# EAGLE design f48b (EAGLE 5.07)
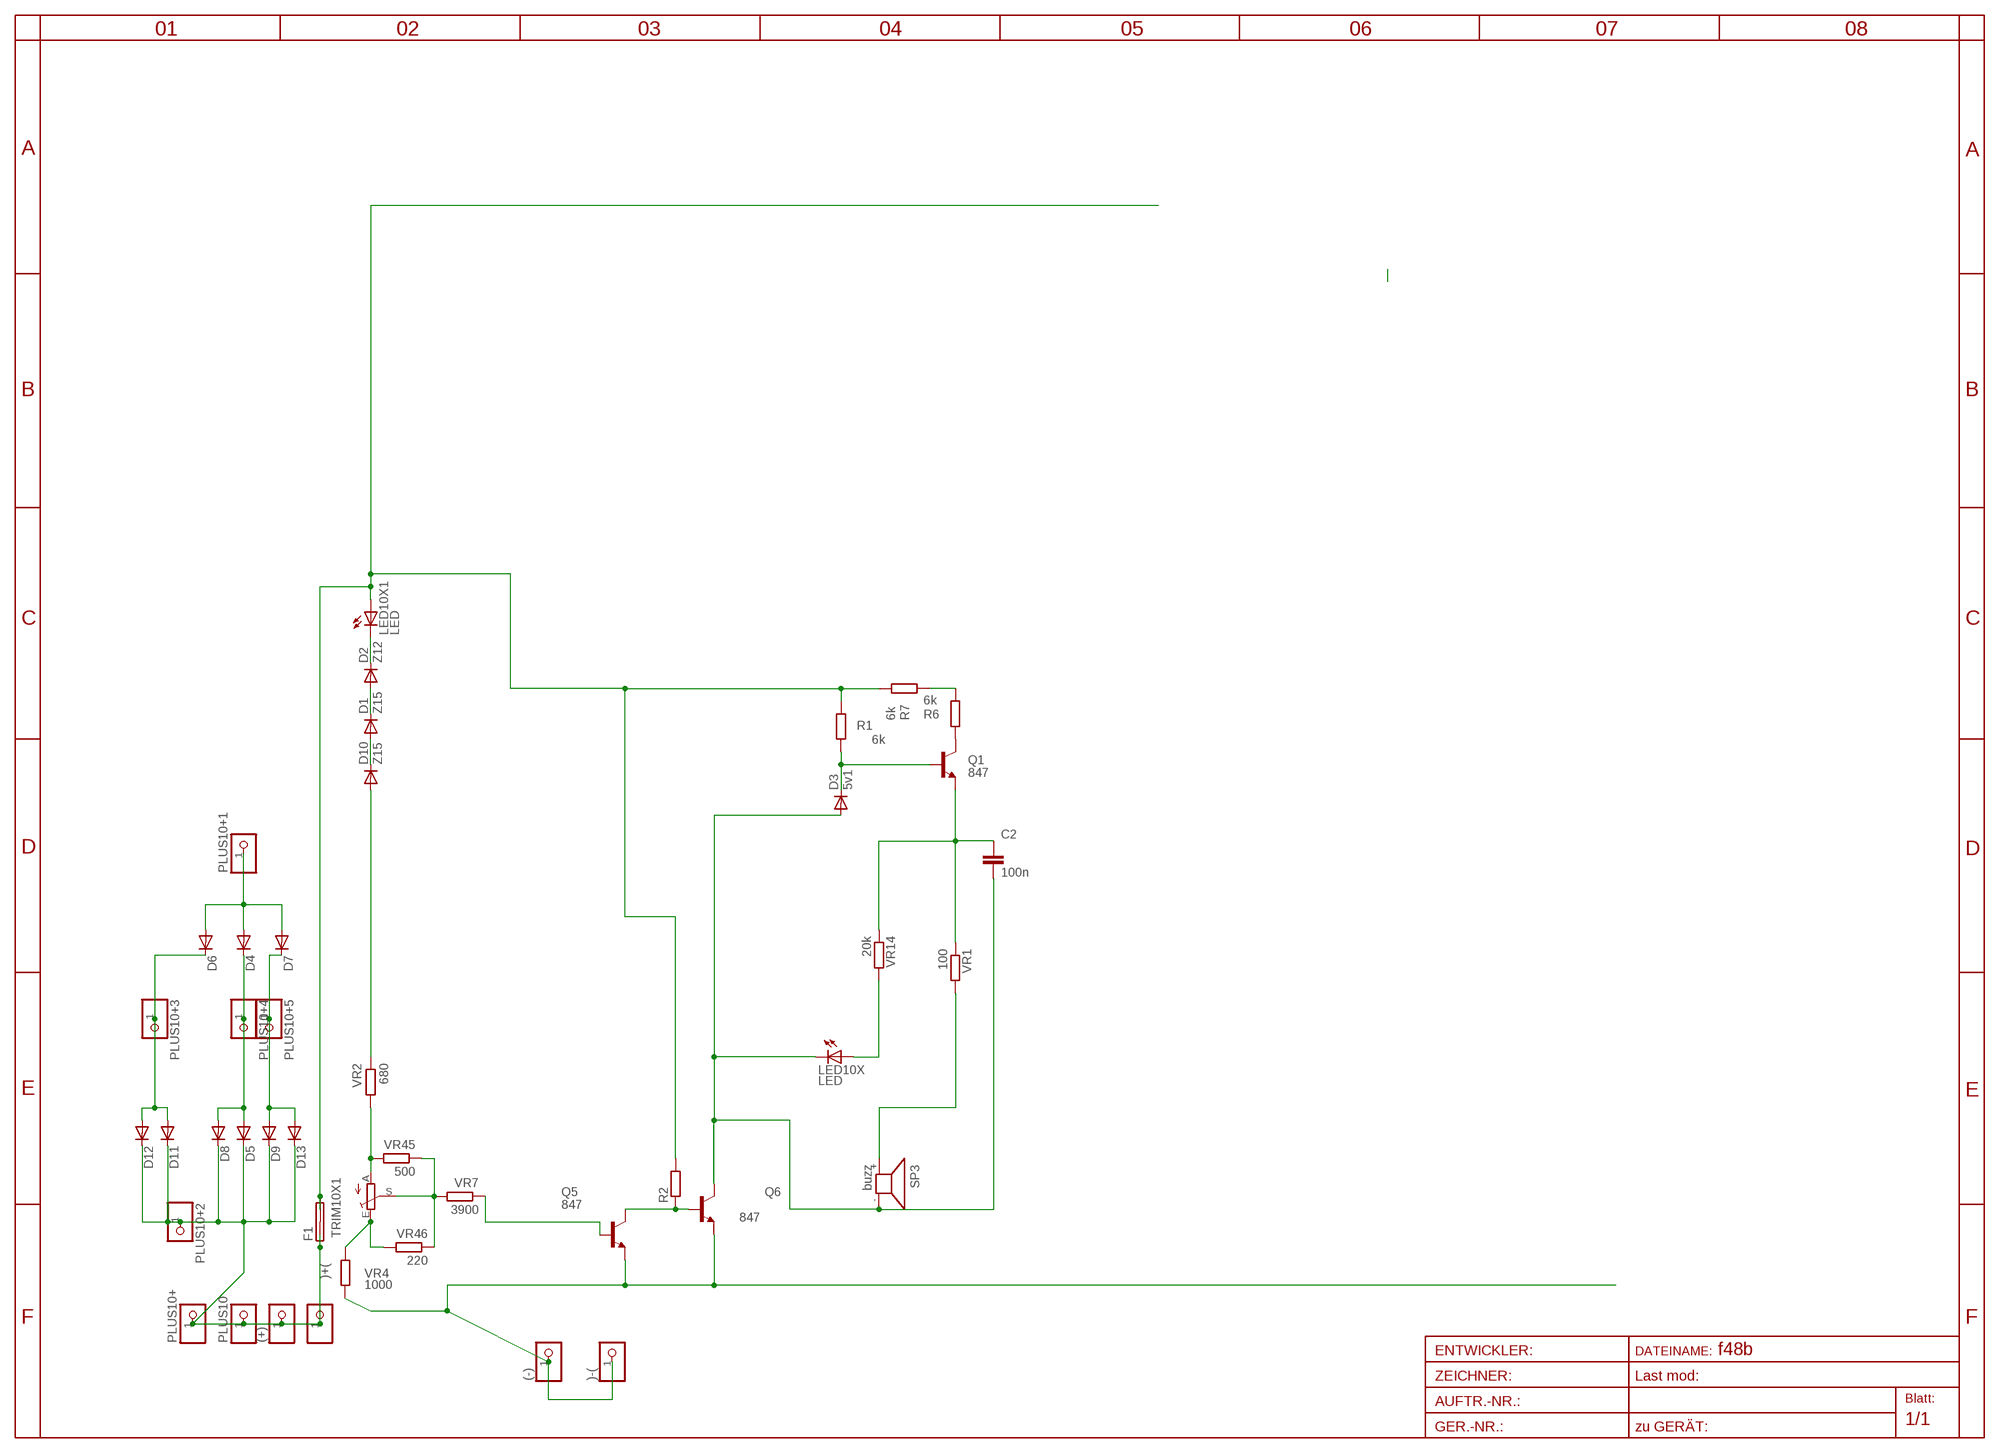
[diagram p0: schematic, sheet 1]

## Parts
(+)  PINHD-1X14.5MM  [1X4MM5]
(-)  PINHD-1X14.5MM  [1X4MM5]
)+(  PINHD-1X11X0.4  [1X01]
)-(  PINHD-1X11X0.4  [1X01]
C2  100n  C-EUC1206  [C1206]
D1  Z15  DIODE-MINIMELF  [MINIMELF]
D2  Z12  DIODE-MINIMELF  [MINIMELF]
D3  5v1  DIODE-MINIMELF  [MINIMELF]
D4  DIODE-SMC  [SMC]
D5  DIODE-SMC  [SMC]
D6  DIODE-SMC  [SMC]
D7  DIODE-SMC  [SMC]
D8  DIODE-SMC  [SMC]
D9  DIODE-SMC  [SMC]
D10  Z15  DIODE-MINIMELF  [MINIMELF]
D11  DIODE-SMC  [SMC]
D12  DIODE-SMC  [SMC]
D13  DIODE-SMC  [SMC]
F1  SHK20L7MM5  [7MM5]
LED10X  LED  LEDCHIPLED_1206  [CHIPLED_1206]
LED10X1  LED  LEDCHIPLED_1206  [CHIPLED_1206]
PLUS10  PINHD-1X14.5MM  [1X4MM5]
PLUS10+  PINHD-1X11X0.4  [1X01]
PLUS10+1  PINHD-1X12MM3  [1X2MM3]
PLUS10+2  PINHD-1X12MM3  [1X2MM3]
PLUS10+3  PINHD-1X12MM3  [1X2MM3]
PLUS10+4  PINHD-1X12MM3  [1X2MM3]
PLUS10+5  PINHD-1X12MM3  [1X2MM3]
Q1  847  BC847CSMD  [SOT23]
Q5  847  BC847CSMD  [SOT23]
Q6  847  BC847CSMD  [SOT23]
R1  6k  R-EU_R1206  [R1206]
R2  R-EU_R1206  [R1206]
R6  6k  R-EU_R1206  [R1206]
R7  6k  R-EU_R1206  [R1206]
SP3  buzz  KSS12017MM  [KSS1202]
TRIM10X1  TRIM_EU-S64W  [S64W]
VR1  100  R-EU_R0805  [R0805]
VR2  680  R-EU_R0805  [R0805]
VR4  1000  R-EU_R0805  [R0805]
VR7  3900  R-EU_R1206  [R1206]
VR14  20k  R-EU_R0805  [R0805]
VR45  500  R-EU_R0805  [R0805]
VR46  220  R-EU_R0805  [R0805]

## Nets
B1: D6.C D11.A D12.A PLUS10+3.1
B2: D7.C D9.A D13.A PLUS10+5.1
B3: D4.C D5.A D8.A PLUS10+4.1
BUZZ+: SP3.+ VR1.2
CHARG: D4.A D6.A D7.A PLUS10+1.1
FPLUS: F1.2A F1.2B LED10X1.A R1.2 R2.2 R7.1
INPLUS: (+).1 )+(.1 D5.C D8.C D9.C D11.C D12.C D13.C F1.1A F1.1B PLUS10+2.1 PLUS10+.1 PLUS10.1
LEDA: LED10X.A VR14.2
N$1: D1.C D2.A
N$2: D3.C Q1.1(B) R1.1
N$3: Q5.3(C) Q6.1(B) R2.1
N$4: D1.A D10.C
N$5: C2.2 D3.A LED10X.C Q6.3(C) SP3.-
N$6: Q1.3(C) R6.2
N$7: TRIM10X1.A VR2.2 VR45.2
N$8: C2.1 Q1.2(E) VR1.1 VR14.1
N$9: D2.C LED10X1.C
N$10: D10.A VR2.1
N$18: R6.1 R7.2
N$22: TRIM10X1.S VR7.2 VR45.1 VR46.1
N$24: TRIM10X1.E VR4.1 VR46.2
N$168: Q5.1(B) VR7.1
VSS: (-).1 )-(.1 Q5.2(E) Q6.2(E) VR4.2

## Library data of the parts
(+) (-) )+( )-( PLUS10 PLUS10+ PLUS10+1-PLUS10+5 = pinhead:PINHD-1X1: PIN HEADER
C2 = rcl:C-EU: CAPACITOR, European symbol
D1-D13 = diode:DIODE-: DIODE
F1 = fuse:SHK20L: FUSE HOLDER 5 x 20 mm, SH contact, SHH1 Schukat, E1073 Buerklin
LED10X LED10X1 = led:LED: LED
Q1 Q5 Q6 = transistor-npn:BC847*: NPN Transistor
R1 R6 R7 VR1 VR2 VR4 VR7 VR14 VR45 VR46 = rcl-2:R-EU_: RESISTOR, European symbol
R2 = rcl:R-EU_: RESISTOR, European symbol
SP3 = buzzer:KSS1201: SPEAKER
TRIM10X1 = pot:TRIM_EU-: POTENTIOMETER

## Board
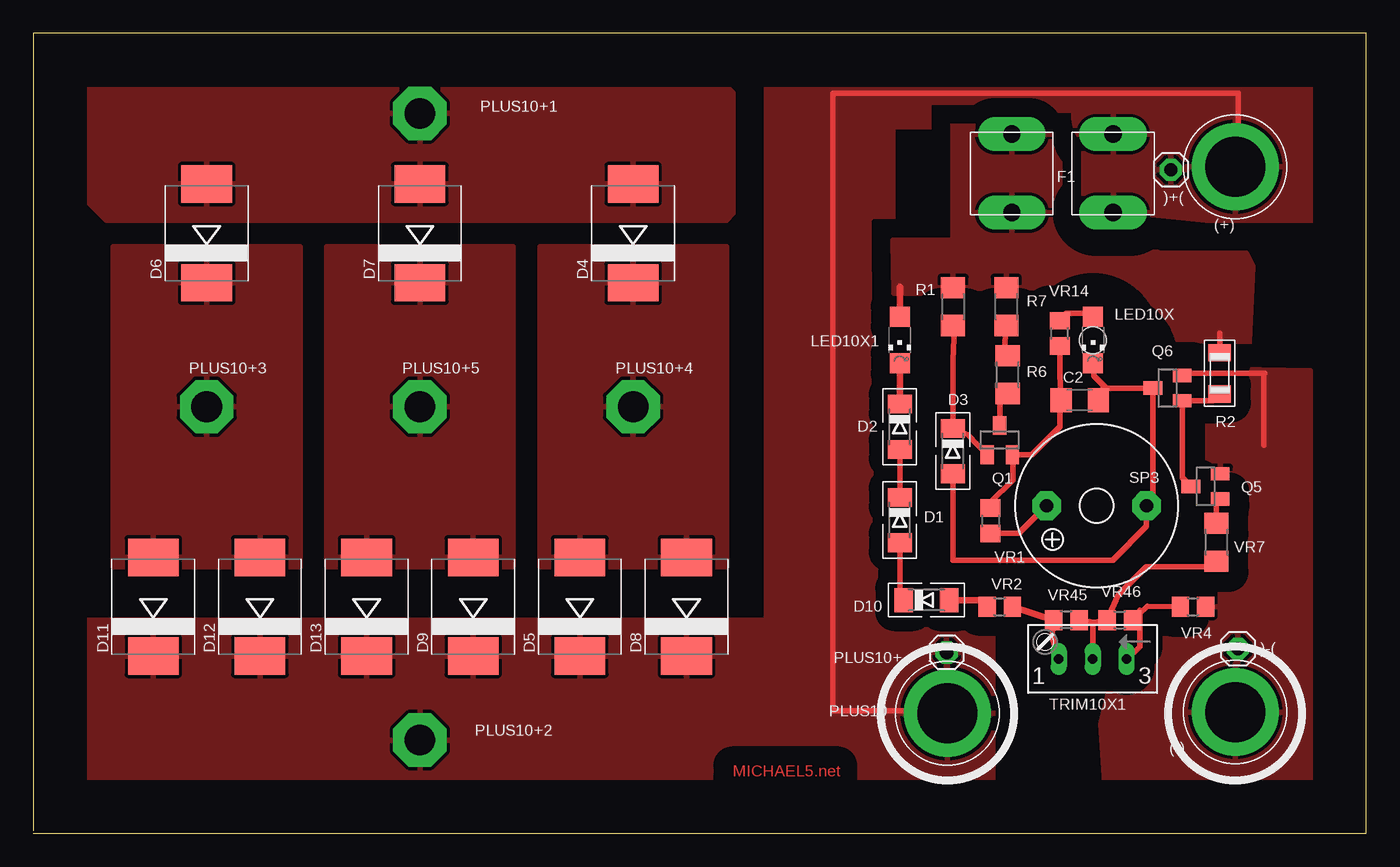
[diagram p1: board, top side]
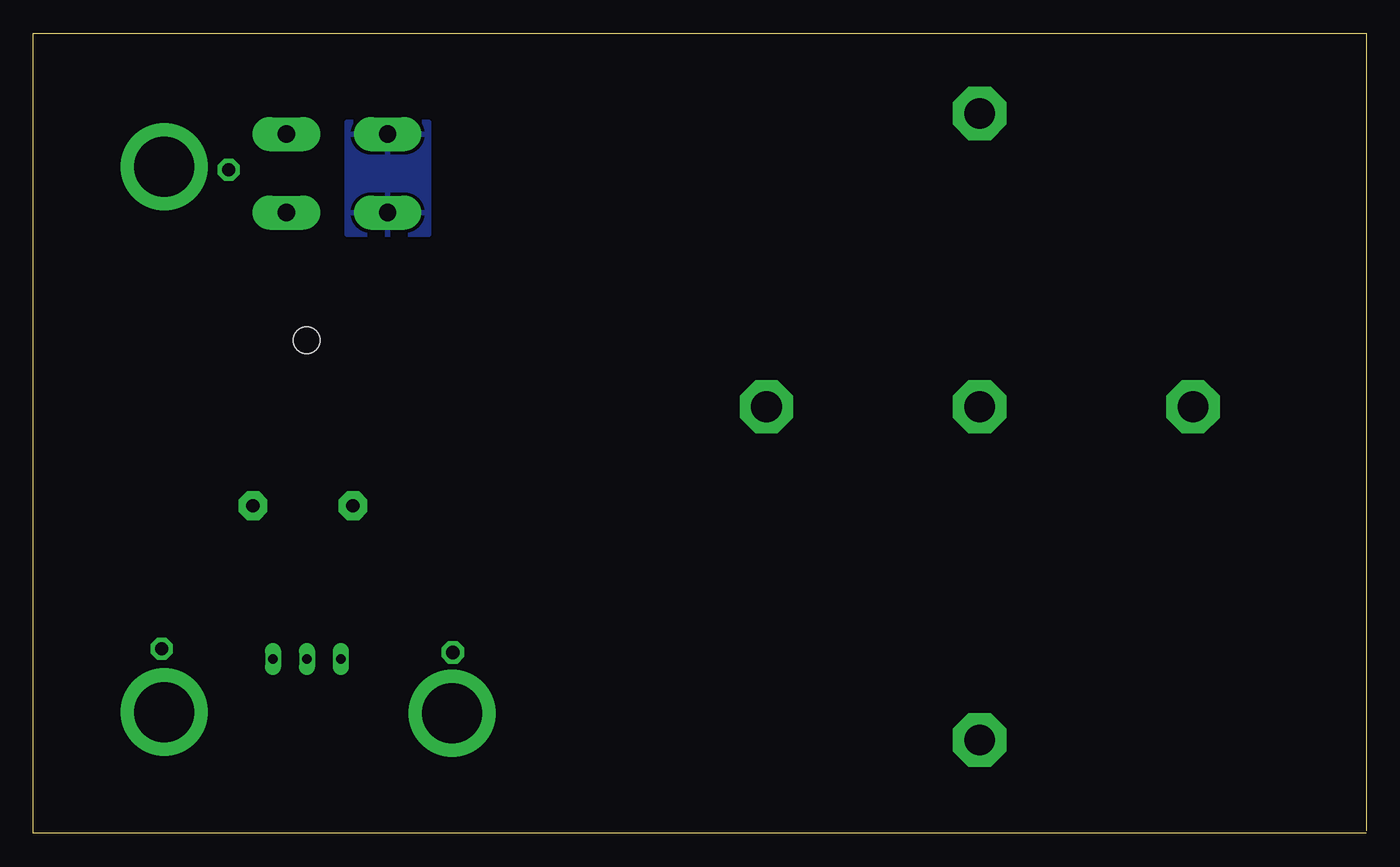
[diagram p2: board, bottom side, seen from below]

Size 100 x 60 mm. Coordinates in mm from the lower left corner, seen from the top.
Outline: 0,0 100,0 100,60 0,60 0,0.2
Copper layers (1*16): Top 0.035mm / dielectric 1.5mm / Bottom 0.035mm
Design rules "default *": minimum track width 8mil, minimum drill 4mil, track to track 8mil, track to pad 8mil, pad to pad 8mil, via to via 8mil, smd to smd 8mil, copper to edge 4mm, drill to drill 8mil, minimum pad ring 10mil, minimum via ring 8mil, stop-mask expansion 4mil, vias tented up to drill 0mil, thermal gap 10mil
Holes 2 mm at 79.5,37

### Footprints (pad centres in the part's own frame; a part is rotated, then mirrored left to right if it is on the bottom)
1X4MM5 = drill 4.5 pad 6.35 round: 1 0,0
1X01 = drill 1 pad 1.676 octagon: 1 0,0
C1206 = smd 1.6 x 1.8: 1 -1.4,0; 2 1.4,0
MINIMELF = smd 1.4 x 1.8: A 1.7,0; C -1.7,0
SMC = smd 2.8 x 3.8: A 3.7,0; C -3.7,0
7MM5 = drill 1.3 pad 2.54 long: 1A -3.8,2.94; 1B -3.8,-2.94; 2A 3.8,2.94; 2B 3.8,-2.94
CHIPLED_1206 = smd 1.5 x 1.5: A 0,-1.75; C 0,1.75
1X2MM3 = drill 2.3 pad 4 octagon: 1 0,0
SOT23 = smd 1 x 1.4: 1 -0.95,-1.1; 2 0.95,-1.1; 3 0,1.1
R1206 = smd 1.6 x 1.803: 1 -1.422,0; 2 1.422,0
R1206' = smd 1.3 x 1.7: 1 -1.55,0; 2 1.55,0
KSS1202 = drill 1 pad 2.159 octagon: + 3.75,0; - -3.75,0
S64W = drill 0.7 long: A 2.54,1.27; E -2.54,1.27; S 0,1.27
R0805 = smd 1.3 x 1.5: 1 -0.95,0; 2 0.95,0

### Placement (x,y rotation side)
(+)  90.17,50 0 top
(-)  90.17,9.1 0 top
)+(  85.34,49.77 0 top
)-(  90.37,13.85 0 top
C2  78.5,32.5 0 top
D1  65,23.5 270 top
D2  65,30.5 270 top
D3  68.98,28.67 270 top
D4  45,45 90 top
D5  41,17 90 top
D6  13,45 90 top
D7  29,45 90 top
D8  49,17 90 top
D9  33,17 90 top
D10  67,17.5 0 top
D11  9,17 90 top
D12  17,17 90 top
D13  25,17 90 top
F1  77.22,49.5 180 top
LED10X  79.5,37 180 top
LED10X1  65,37 180 top
PLUS10  68.58,9 0 top
PLUS10+  68.52,13.57 0 top
PLUS10+1  29,54 0 top
PLUS10+2  29,7 0 top
PLUS10+3  13,32 0 top
PLUS10+4  45,32 0 top
PLUS10+5  29,32 0 top
Q1  72.5,29.5 0 top
Q5  87.95,26.02 90 top
Q6  85.09,33.4 90 top
R1  69,39.5 90 top
R2  [R1206']  89,34.5 90 top
R6  73.1,34.4 270 top
R7  73,39.5 270 top
SP3  79.77,24.57 180 top
TRIM10X1  79.47,14.35 180 top
VR1  71.81,23.44 270 top
VR2  72.5,17 0 top
VR4  87,17 0 top
VR7  88.77,21.83 270 top
VR14  77,37.5 90 top
VR45  77.5,16 180 top
VR46  81.5,16 0 top

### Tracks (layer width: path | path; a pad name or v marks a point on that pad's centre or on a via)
B1
  pour Top (isolate 1.422, rank 4): 6,44 20,44 20,20 6,20
B2
  pour Top (isolate 1.422, rank 4): 36,44 36,20 22,20 22,44
B3
  pour Top (isolate 1.422, rank 4): 52,44 52,20 38,20 38,44
BUZZ+
  Top 0.406: VR1.2 73.94,22.49 SP3.+
CHARG
  pour Top (isolate 1.422, rank 4): 3,58.5 49.5,58.5 52.5,55.5 52.5,46.5 52,46 5.5,46 3,48.5
FPLUS
  Top 0.406: R2.2 89,37.5
  Top 0.5: LED10X1.A 65,41
  pour Top (isolate 2, rank 2): 69,53.33 77,53.33 77,45 80.5,45 84.5,43.5 91,43.5 91.5,42.5 91.15,35.24 86,35.24 86,36.5 arc60 82.5,40.5 64.56,40.5 64.5,44.5 69,44.5
  pour Bottom (isolate 1.5, rank 4): 70.36,53.33 76.45,53.33 76.45,44.94 70.36,44.94
INPLUS
  Top 0.406: (+).1 90.4,50 90.4,55.5 60,55.5 60,9.2 68.58,9.2 PLUS10.1
  pour Top (isolate 1.422, rank 3): 88,46 96,46 96,47 96,58 55,58 55,55.5 55,16 2.5,16 2.5,12 2.5,4 72,4 72,5.5 72,17 64.5,17 64.5,53 78,53 78,47
LEDA
  Top 0.406: VR14.2 77.19,38.69 77.5,39 79.17,39 LED10X.A
N$1
  Top 0.406: D1.C D2.A
N$2
  Top 0.406: R1.1 69.08,37.08 69,35.5 69,30.5 | 69,30.5 69.11,30.5 D3.C | Q1.1 70.1,29.9 69,30.5
N$3
  Top 0.406: Q5.3 86.19,26.68 Q6.1 88.5,32.45 R2.1
N$4
  Top 0.406: D10.C 65.3,17.7 65,18 D1.A
N$5
  Top 0.406: D3.A 69,23.98 69,20.5 81,20.5 83.52,23.02 SP3.- 83.99,25.03 Q6.3 80.5,33.4 | 80.5,33.4 80.24,33.4 C2.2 | LED10X.C 79.59,34.31 80.5,33.4
N$6
  Top 0.406: Q1.3 72.5,32.88 R6.2
N$7
  Top 0.406: TRIM10X1.A 76.44,14.73 VR45.2
  Top 0.5: VR2.2 VR45.2
N$8
  Top 0.406: VR1.1 71.81,24.81 73.5,26.5 73.5,28.35 Q1.2 74.9,28.4 77,30.5 77,32.96 C2.1 77,34.5 VR14.1
N$9
  Top 0.5: D2.C LED10X1.C
N$10
  Top 0.5: D10.A 71.05,17.5 VR2.1
N$18
  Top 0.406: R7.2 72.8,36.02 R6.1
N$22
  Top 0.406: VR7.2 88.36,20 83.5,20 81.39,17.89 VR46.1 79.59,15.82 VR45.1 79.47,15.77 TRIM10X1.S
N$24
  Top 0.406: TRIM10X1.E 82.08,13.08 83,14 83,16.73 VR46.2 83.58,17.02 VR4.1
N$168
  Top 0.406: VR7.1 88.77,24.8 Q5.1
VSS
  Top 0.406: Q6.2 86.5,34.35 86.5,34.5 92.3,34.5 | 92.3,34.5 92.4,34.5 | 92.3,34.5 92.3,29.1
  pour Top (isolate 1.5, rank 2): 80.1,8.2 86.6,34.9 95.8,34.7 96.3,4.1 80.4,3.7

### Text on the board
Top: MICHAEL5.net
tTest: 4v4
Document: 1m | 10u | 10u | 300u | 2mA | 500u | 1m | 2m | 300u | 300u | 30u | 5m | 14m | 12m | 500u | 5m | 5m | 5m | 5m | 5m | 5m | 40m | 40m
